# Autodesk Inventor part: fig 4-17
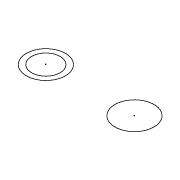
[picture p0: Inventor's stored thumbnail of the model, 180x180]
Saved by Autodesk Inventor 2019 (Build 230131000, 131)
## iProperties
Created: 2005-02
Part Number: fig 4-17
Document SubType Name: Modeling
Designer: CADCIM
Manufacturer: Standard
Standards Organization: Custom
Density: 1 g/cm^3
Material: Generic
Appearance: Default
Author: CADCIM
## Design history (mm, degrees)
sketch "Sketch1"
  geometry: C1 r 7.935 at (-23.563, 7.599); C2 r 7.935 at (12.452, 7.599); C3 r 5.782 at (-23.563, 7.599)
  constraints: 3 centre point, 1 coincident, 1 equal radius, 1 other
